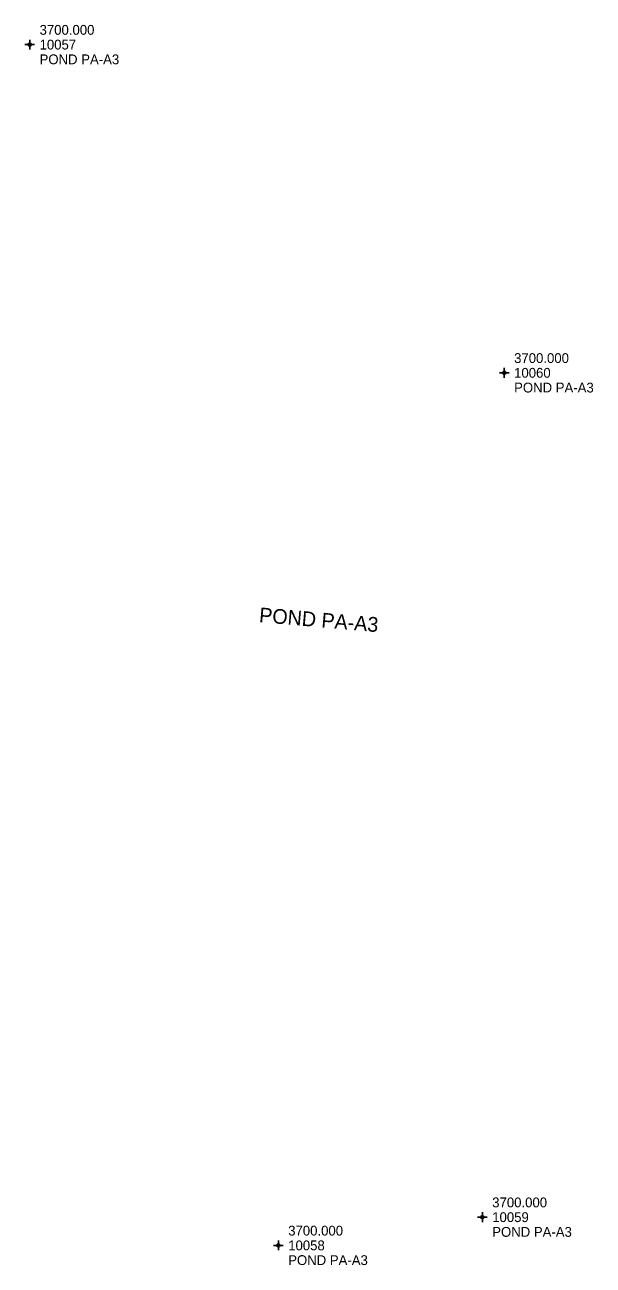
# Model space of a CAD drawing. Extents: x 352921 to 392463, y 10654752 to 10749237.
# Drawn here: x 384512 to 384801, y 10655676 to 10656307 of the extents above; entities that cross this region are included whole.
import ezdxf

# ---------------------------------------------------------------- set-up
doc = ezdxf.new("R2010")
doc.units = 0
for name, color, linetype in [('CK_#', 7, 'Continuous'), ('CK_DES', 7, 'Continuous'), ('CK_ELEV', 7, 'Continuous'), ('CONTROL', 7, 'Continuous'), ('ROAD NAMES', 7, 'Continuous')]:
    doc.layers.add(name, color=color, linetype=linetype)

msp = doc.modelspace()

# ---------------------------------------------------------------- linework, layer by layer
at = {"layer": 'CK_#'}
for p, q in [((384516.6, 10656296.81), (384511.6, 10656296.81)), ((384514.1, 10656299.31), (384514.1, 10656294.31)), ((384757.9, 10656129.82), (384752.9, 10656129.82)), ((384755.4, 10656132.32), (384755.4, 10656127.32)), ((384746.77, 10655700.25), (384741.77, 10655700.25)), ((384744.27, 10655702.75), (384744.27, 10655697.75)), ((384643.03, 10655685.88), (384638.03, 10655685.88)), ((384640.53, 10655688.38), (384640.53, 10655683.38))]:
    msp.add_line(p, q, dxfattribs=at)
at = {"layer": 'CONTROL'}
for p, q in [((384514.01, 10656296.9), (384513.71, 10656297.2)), ((384514.1, 10656296.81), (384514.1, 10656296.81)), ((384514.19, 10656296.9), (384514.47, 10656297.17)), ((384513.73, 10656296.44), (384514.01, 10656296.72)), ((384514.47, 10656296.44), (384514.19, 10656296.72)), ((384755.31, 10656129.91), (384755.01, 10656130.2)), ((384755.03, 10656129.44), (384755.31, 10656129.72)), ((384755.4, 10656129.82), (384755.4, 10656129.82)), ((384755.49, 10656129.9), (384755.77, 10656130.18)), ((384755.77, 10656129.44), (384755.49, 10656129.72)), ((384744.18, 10655700.34), (384743.89, 10655700.64)), ((384743.9, 10655699.88), (384744.19, 10655700.16)), ((384744.27, 10655700.25), (384744.27, 10655700.25)), ((384744.37, 10655700.34), (384744.64, 10655700.62)), ((384744.65, 10655699.88), (384744.37, 10655700.16)), ((384640.43, 10655685.97), (384640.14, 10655686.27)), ((384640.15, 10655685.51), (384640.44, 10655685.79)), ((384640.53, 10655685.88), (384640.53, 10655685.88)), ((384640.62, 10655685.97), (384640.89, 10655686.24)), ((384640.9, 10655685.51), (384640.62, 10655685.79))]:
    msp.add_line(p, q, dxfattribs=at)
for centre, radius in [((384514.1, 10656296.81), 0.8), ((384514.1, 10656296.81), 0.8), ((384514.1, 10656296.81), 0.125), ((384755.4, 10656129.82), 0.8), ((384755.4, 10656129.82), 0.8), ((384755.4, 10656129.82), 0.125), ((384744.27, 10655700.25), 0.8), ((384744.27, 10655700.25), 0.8), ((384744.27, 10655700.25), 0.125), ((384640.53, 10655685.88), 0.8), ((384640.53, 10655685.88), 0.8), ((384640.53, 10655685.88), 0.125)]:
    msp.add_circle(centre, radius, dxfattribs=at)

# ---------------------------------------------------------------- texts
at = {"layer": 'CK_#'}
for s, p in [('10057', (384519.1, 10656294.31)), ('10060', (384760.4, 10656127.32)), ('10059', (384749.27, 10655697.75)), ('10058', (384645.53, 10655683.38))]:
    msp.add_text(s, height=5, dxfattribs=at).set_placement(p)
at = {"layer": 'CK_DES'}
for p in [(384519.1, 10656286.81), (384760.4, 10656119.82), (384749.27, 10655690.25), (384645.53, 10655675.88)]:
    msp.add_text('POND PA-A3', height=5, dxfattribs=at).set_placement(p)
at = {"layer": 'CK_ELEV'}
for p in [(384519.1, 10656301.81), (384760.4, 10656134.82), (384749.27, 10655705.25), (384645.53, 10655690.88)]:
    msp.add_text('3700.000', height=5, dxfattribs=at).set_placement(p)
at = {"layer": 'ROAD NAMES'}
msp.add_text('POND PA-A3', height=7.5, rotation=355.15195, dxfattribs=at).set_placement((384630.53, 10656003.01))

doc.saveas('drawing.dxf')
